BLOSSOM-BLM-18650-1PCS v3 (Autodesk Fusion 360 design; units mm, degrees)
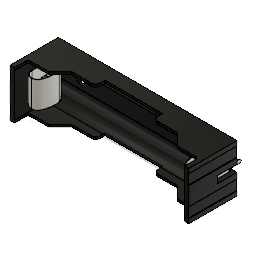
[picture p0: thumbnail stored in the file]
sketch "bottom"
  dimension "d1" = 78
  dimension "d2" = 40
  dimension "d3" = 3
  dimension "d4" = 3
  dimension "d5" = 3
  dimension "d6" = 3
  dimension "d7" = 10.5
  dimension "d8" = 10.5
  dimension "d9" = 10.5
  dimension "d10" = 10.5
  dimension "d11" = 0.75
  dimension "d12" = 0.75
  dimension "d13" = 1.1
  dimension "d14" = 1.1
  dimension "d15" = 1.9
  dimension "d16" = 1.9
  dimension "d18" = 1.6
  dimension "d19" = 1.6
  dimension "d20" = 2.5
  dimension "d21" = 3
  dimension "d22" = 9
  dimension "d23" = 2.5
  dimension "d24" = 3
  dimension "d25" = 9
  dimension "d26" = 2.5
  dimension "d27" = 3
  dimension "d28" = 9
  dimension "d29" = 2.5
  dimension "d30" = 3
  dimension "d31" = 9
  dimension "d32" = 11
  dimension "d33" = 11
  dimension "d34" = 11
  dimension "d35" = 11
  dimension "d36" = 4.5
  dimension "d37" = 4.5
  dimension "d38" = 1
  dimension "d39" = 2
  dimension "d40" = 4.5
  dimension "d41" = 1
  dimension "d42" = 4.5
  dimension "d43" = 2
  dimension "d44" = 4.5
  dimension "d45" = 4.5
  dimension "d46" = 4.5
  dimension "d47" = 4.5
  dimension "d48" = 4.5
  dimension "d49" = 4.5
  dimension "d50" = 4.5
  dimension "d51" = 4.5
extrude "Extrude1" new body sketch "bottom" blind 21.1
work_plane "WorkPlane1" AlongDistance -8.6
sketch "offset" plane through (39, 20, 8.6) normal (0, 0, -1) x axis (1, 0, 0)
  dimension "d55" = 0.5
  dimension "d56" = 0.5
  dimension "d57" = 0.5
  dimension "d58" = 0.5
  dimension "d59" = 0.5
  dimension "d60" = 0.5
  dimension "d61" = 0.5
  dimension "d62" = 0.5
loft "Loft1" sketch "bottom" + "offset"
loft "Loft2" sketch "bottom" + "offset"
loft "Loft3" sketch "bottom" + "offset"
loft "Loft4" sketch "bottom" + "offset"
sketch "top" plane through (0, 0, 21.1) normal (0, 0, 1) x axis (1, 0, 0)
extrude "Extrude2" cut sketch "top" against normal blind 20.1
extrude "Extrude3" cut sketch "bottom" to an object
fillet "Fillet1" radius 6
sketch "sideA" plane through (0, 40, 0) normal (0, 1, 0) x axis (-1, 0, 0)
  dimension "d82" = 10.5
sketch "sideB" plane through (0, 0, 0) normal (0, -1, 0) x axis (1, 0, 0)
extrude "Extrude4" cut sketch "sideB" to an object
extrude "Extrude5" cut sketch "sideA" to an object
component_insert "Component Insert1"
component_insert "Component Insert3"
position "Position1"
sketch "Sketch8" plane through (0, 20.75, 0) normal (0, 1, 0) x axis (-1, 0, 0)
  dimension "d90" = 9
extrude "Extrude6" cut sketch "Sketch8" to an object
work_plane "WorkPlane1" AlongDistance -10.5
split "Split1"
work_plane "WorkPlane2" AlongDistance -10.5
split "Split2"
move "Move1"
combine "Combine1"
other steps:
create_component "CreateComponent1"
